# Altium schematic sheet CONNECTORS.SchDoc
size A3; SheetNumber: 2; SheetTotal: 2
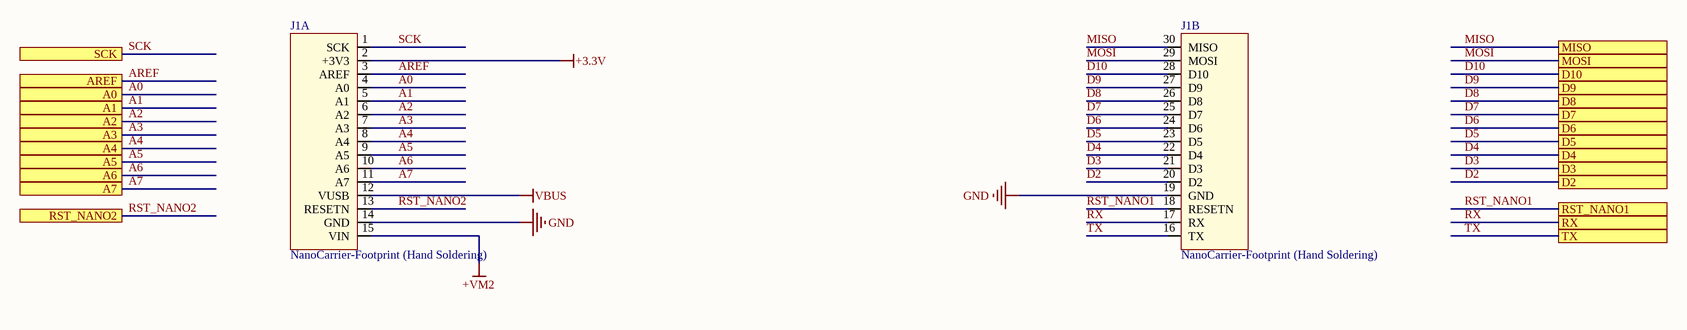
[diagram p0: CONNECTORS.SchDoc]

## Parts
J1  NanoCarrier-Footprint (Hand Soldering)  [NanoCarrier-Footprint (Hand Soldering)-Footprint-1]  (parts A,B of 2)  (no BOM)

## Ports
A0, A1, A2, A3, A4, A5, A6, A7, AREF, D2, D3, D4, D5, D6, D7, D8, D9, D10, MISO, MOSI, RST_NANO1, RST_NANO2, RX, SCK, TX

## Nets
+3.3V: J1.2(+3V3)
+VM2: J1.15(VIN)
GND: J1.14(GND) J1.19(GND)
VBUS: J1.12(VUSB)
A0: J1.4(A0) ; port A0
A1: J1.5(A1) ; port A1
A2: J1.6(A2) ; port A2
A3: J1.7(A3) ; port A3
A4: J1.8(A4) ; port A4
A5: J1.9(A5) ; port A5
A6: J1.10(A6) ; port A6
A7: J1.11(A7) ; port A7
AREF: J1.3(AREF) ; port AREF
D2: J1.20(D2) ; port D2
D3: J1.21(D3) ; port D3
D4: J1.22(D4) ; port D4
D5: J1.23(D5) ; port D5
D6: J1.24(D6) ; port D6
D7: J1.25(D7) ; port D7
D8: J1.26(D8) ; port D8
D9: J1.27(D9) ; port D9
D10: J1.28(D10) ; port D10
MISO: J1.30(MISO) ; port MISO
MOSI: J1.29(MOSI) ; port MOSI
RST_NANO1: J1.18(RESETN) ; port RST_NANO1
RST_NANO2: J1.13(RESETN) ; port RST_NANO2
RX: J1.17(RX) ; port RX
SCK: J1.1(SCK) ; port SCK
TX: J1.16(TX) ; port TX

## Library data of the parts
J1 = AF0004-A.2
